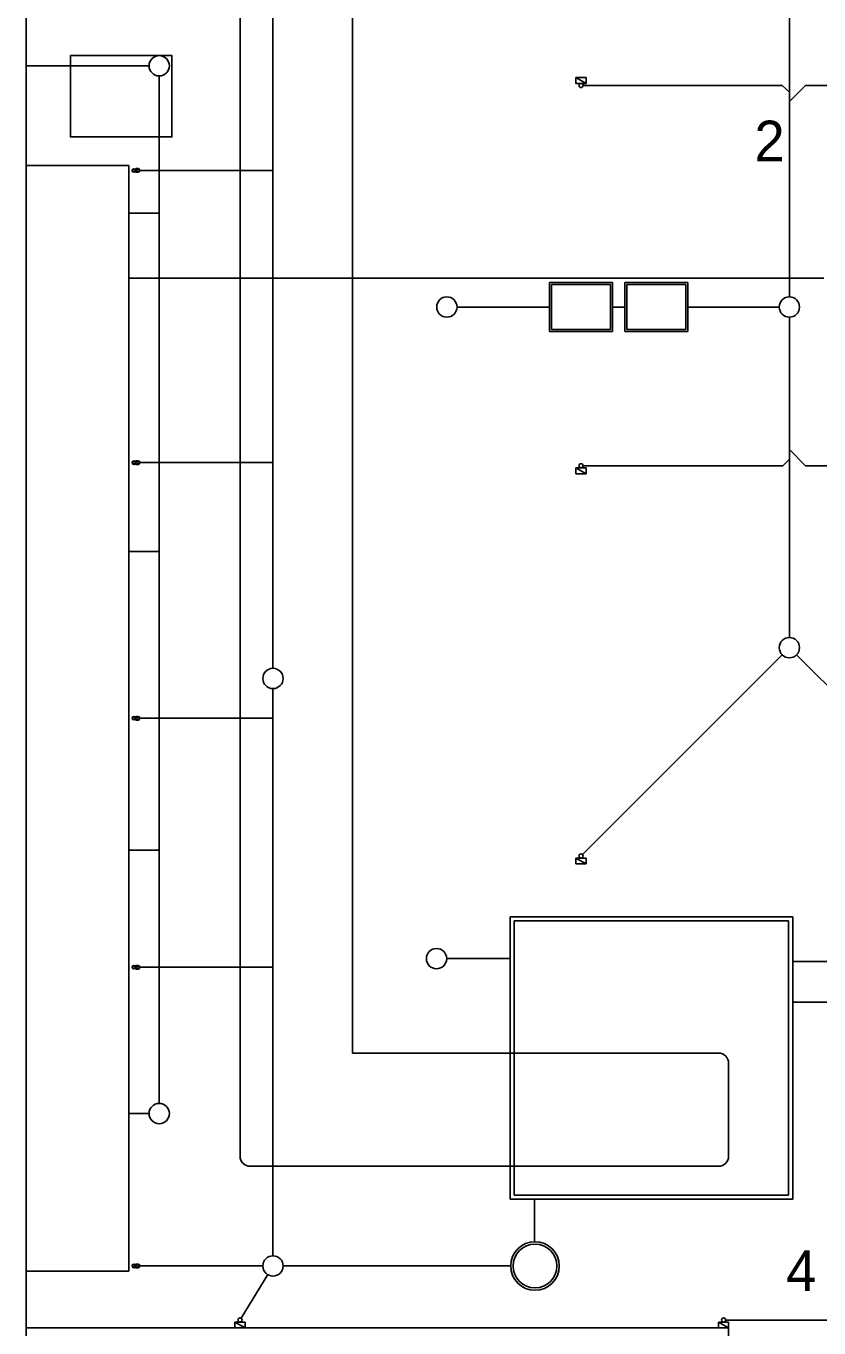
# Model space of a CAD drawing. Extents: x -263964 to -263544, y -1242317 to -1242020.
# Drawn here: x -263964.1 to -263925.1, y -1242255 to -1242190.9 of the extents above; entities that cross this region are included whole.
import ezdxf

# ---------------------------------------------------------------- set-up
doc = ezdxf.new("R2010")
doc.units = 0
for name, color, linetype in [('KFA_KOORDINACNA_SITUACIA_DSP_SEDA', 7, 'Continuous'), ('KFA_SO_50-2_POZIARNY_VODOVOD_BODY', 7, 'Continuous'), ('RAM_NA_TLAC_A3_1-100', 7, 'Continuous')]:
    doc.layers.add(name, color=color, linetype=linetype)

msp = doc.modelspace()

# ---------------------------------------------------------------- linework, layer by layer
at = {"layer": 'KFA_KOORDINACNA_SITUACIA_DSP_SEDA'}
for p, q in [((-263948.093, -1242087.901), (-263948.093, -1242241.458)), ((-263953.617, -1242244.458), (-263953.617, -1242093.307)), ((-263926.593, -1242155.252), (-263926.593, -1242204.252)), ((-263952, -1242222.527), (-263952, -1242182)), ((-263958.097, -1242192.883), (-263964.149, -1242192.883)), ((-263957.597, -1242243.932), (-263957.597, -1242193.383)), ((-263937.093, -1242193.752), (-263937.093, -1242193.462)), ((-263937.093, -1242193.462), (-263936.593, -1242193.462)), ((-263936.593, -1242193.752), (-263937.093, -1242193.462)), ((-263936.593, -1242193.752), (-263937.093, -1242193.462)), ((-263937.093, -1242193.462), (-263937.093, -1242193.752)), ((-263936.593, -1242193.752), (-263937.093, -1242193.752)), ((-263937.093, -1242193.752), (-263936.593, -1242193.752)), ((-263936.743, -1242193.852), (-263926.953, -1242193.852)), ((-263936.593, -1242193.462), (-263936.593, -1242193.752)), ((-263926.953, -1242193.852), (-263926.593, -1242194.178)), ((-263925.798, -1242193.852), (-263926.593, -1242194.648)), ((-263920.944, -1242193.852), (-263925.798, -1242193.852)), ((-263964.149, -1242197.782), (-263959.093, -1242197.782)), ((-263964.149, -1242197.782), (-263959.097, -1242197.782)), ((-263964.149, -1242252.182), (-263964.149, -1242197.782)), ((-263964.149, -1242197.782), (-263959.097, -1242197.782)), ((-263959.097, -1242197.782), (-263959.093, -1242252.182)), ((-263959.097, -1242197.782), (-263959.097, -1242252.182)), ((-263959.093, -1242197.782), (-263959.093, -1242252.182)), ((-263958.799, -1242197.962), (-263958.762, -1242197.962)), ((-263958.799, -1242198.102), (-263958.762, -1242198.102)), ((-263958.762, -1242197.962), (-263958.742, -1242197.942)), ((-263958.762, -1242198.102), (-263958.742, -1242198.122)), ((-263958.742, -1242197.942), (-263958.637, -1242197.942)), ((-263958.742, -1242198.122), (-263958.637, -1242198.122)), ((-263958.575, -1242198.032), (-263952, -1242198.032)), ((-263959.097, -1242200.132), (-263957.597, -1242200.132)), ((-263959.097, -1242203.332), (-263958.097, -1242203.332)), ((-263924.893, -1242203.332), (-263958.097, -1242203.332)), ((-263938.393, -1242203.552), (-263935.293, -1242203.552)), ((-263938.393, -1242205.952), (-263938.393, -1242203.552)), ((-263938.293, -1242205.852), (-263938.293, -1242203.652)), ((-263938.293, -1242203.652), (-263935.393, -1242203.652)), ((-263935.393, -1242205.852), (-263935.393, -1242203.652)), ((-263935.293, -1242205.952), (-263935.293, -1242203.552)), ((-263934.693, -1242203.552), (-263931.593, -1242203.552)), ((-263934.693, -1242203.552), (-263934.693, -1242205.952)), ((-263934.593, -1242203.652), (-263934.593, -1242205.852)), ((-263934.593, -1242203.652), (-263931.693, -1242203.652)), ((-263931.693, -1242203.652), (-263931.693, -1242205.852)), ((-263931.593, -1242203.552), (-263931.593, -1242205.952)), ((-263938.393, -1242204.752), (-263942.945, -1242204.752)), ((-263934.693, -1242204.752), (-263935.293, -1242204.752)), ((-263927.093, -1242204.752), (-263931.593, -1242204.752)), ((-263926.593, -1242221.011), (-263926.593, -1242205.252)), ((-263935.293, -1242205.952), (-263938.393, -1242205.952)), ((-263935.393, -1242205.852), (-263938.293, -1242205.852)), ((-263931.593, -1242205.952), (-263934.693, -1242205.952)), ((-263931.693, -1242205.852), (-263934.593, -1242205.852)), ((-263925.798, -1242212.562), (-263926.593, -1242211.767)), ((-263958.799, -1242212.337), (-263958.762, -1242212.337)), ((-263958.762, -1242212.337), (-263958.742, -1242212.317)), ((-263958.742, -1242212.317), (-263958.637, -1242212.317)), ((-263958.575, -1242212.407), (-263952, -1242212.407)), ((-263926.919, -1242212.562), (-263926.593, -1242212.237)), ((-263958.799, -1242212.477), (-263958.762, -1242212.477)), ((-263958.762, -1242212.477), (-263958.742, -1242212.497)), ((-263958.742, -1242212.497), (-263958.637, -1242212.497)), ((-263937.093, -1242212.952), (-263937.093, -1242212.662)), ((-263937.093, -1242212.662), (-263936.593, -1242212.662)), ((-263936.593, -1242212.952), (-263937.093, -1242212.662)), ((-263936.593, -1242212.952), (-263937.093, -1242212.662)), ((-263937.093, -1242212.662), (-263937.093, -1242212.952)), ((-263936.593, -1242212.952), (-263937.093, -1242212.952)), ((-263937.093, -1242212.952), (-263936.593, -1242212.952)), ((-263936.743, -1242212.562), (-263926.919, -1242212.562)), ((-263936.593, -1242212.662), (-263936.593, -1242212.952)), ((-263916.443, -1242212.562), (-263925.798, -1242212.562)), ((-263959.097, -1242216.782), (-263957.597, -1242216.782)), ((-263936.772, -1242231.691), (-263926.947, -1242221.865)), ((-263916.414, -1242231.691), (-263926.24, -1242221.865)), ((-263952, -1242251.432), (-263952, -1242223.527)), ((-263958.799, -1242224.912), (-263958.762, -1242224.912)), ((-263958.799, -1242225.052), (-263958.762, -1242225.052)), ((-263958.762, -1242224.912), (-263958.742, -1242224.892)), ((-263958.762, -1242225.052), (-263958.742, -1242225.072)), ((-263958.742, -1242224.892), (-263958.637, -1242224.892)), ((-263958.742, -1242225.072), (-263958.637, -1242225.072)), ((-263958.575, -1242224.982), (-263952, -1242224.982)), ((-263959.097, -1242231.482), (-263957.597, -1242231.482)), ((-263937.093, -1242231.862), (-263936.593, -1242231.862)), ((-263937.093, -1242232.152), (-263937.093, -1242231.862)), ((-263937.093, -1242231.862), (-263936.593, -1242232.152)), ((-263937.093, -1242231.862), (-263936.593, -1242232.152)), ((-263936.593, -1242231.862), (-263937.093, -1242231.862)), ((-263936.593, -1242232.152), (-263937.093, -1242232.152)), ((-263936.593, -1242231.862), (-263936.593, -1242232.152)), ((-263936.593, -1242232.152), (-263936.593, -1242231.862)), ((-263926.43, -1242234.749), (-263940.33, -1242234.749)), ((-263940.33, -1242234.749), (-263940.33, -1242248.649)), ((-263926.43, -1242248.649), (-263926.43, -1242234.749)), ((-263926.63, -1242234.949), (-263940.13, -1242234.949)), ((-263940.13, -1242234.949), (-263940.13, -1242248.449)), ((-263926.63, -1242248.449), (-263926.63, -1242234.949)), ((-263958.799, -1242237.162), (-263958.762, -1242237.162)), ((-263958.799, -1242237.302), (-263958.762, -1242237.302)), ((-263958.762, -1242237.162), (-263958.742, -1242237.142)), ((-263958.762, -1242237.302), (-263958.742, -1242237.322)), ((-263958.742, -1242237.142), (-263958.637, -1242237.142)), ((-263958.742, -1242237.322), (-263958.637, -1242237.322)), ((-263958.575, -1242237.232), (-263952, -1242237.232)), ((-263940.33, -1242236.811), (-263943.454, -1242236.811)), ((-263919.13, -1242236.949), (-263926.43, -1242236.949)), ((-263907.219, -1242238.949), (-263926.43, -1242238.949)), ((-263930.081, -1242241.458), (-263948.093, -1242241.458)), ((-263929.582, -1242246.53), (-263929.581, -1242241.959)), ((-263959.097, -1242244.432), (-263958.097, -1242244.432)), ((-263953.617, -1242244.458), (-263953.619, -1242246.529)), ((-263953.119, -1242247.03), (-263930.082, -1242247.03)), ((-263940.33, -1242248.649), (-263926.43, -1242248.649)), ((-263940.13, -1242248.449), (-263926.63, -1242248.449)), ((-263939.13, -1242248.649), (-263939.13, -1242250.737)), ((-263958.799, -1242251.862), (-263958.762, -1242251.862)), ((-263958.799, -1242252.002), (-263958.762, -1242252.002)), ((-263958.762, -1242251.862), (-263958.742, -1242251.842)), ((-263958.762, -1242252.002), (-263958.742, -1242252.022)), ((-263958.742, -1242251.842), (-263958.637, -1242251.842)), ((-263958.742, -1242252.022), (-263958.637, -1242252.022)), ((-263958.575, -1242251.932), (-263952.5, -1242251.932)), ((-263940.302, -1242251.932), (-263951.5, -1242251.932)), ((-263959.093, -1242252.182), (-263964.149, -1242252.182)), ((-263959.093, -1242252.182), (-263964.149, -1242252.182)), ((-263959.097, -1242252.182), (-263964.149, -1242252.182)), ((-263953.57, -1242254.506), (-263952.26, -1242252.359)), ((-263953.87, -1242254.692), (-263953.37, -1242254.692)), ((-263953.87, -1242254.982), (-263953.87, -1242254.692)), ((-263953.87, -1242254.692), (-263953.37, -1242254.982)), ((-263953.87, -1242254.692), (-263953.37, -1242254.982)), ((-263953.37, -1242254.692), (-263953.87, -1242254.692)), ((-263953.37, -1242254.692), (-263953.37, -1242254.982)), ((-263953.37, -1242254.982), (-263953.37, -1242254.692)), ((-263930.08, -1242254.692), (-263929.58, -1242254.692)), ((-263930.08, -1242254.982), (-263930.08, -1242254.692)), ((-263930.08, -1242254.692), (-263929.58, -1242254.982)), ((-263930.08, -1242254.692), (-263929.58, -1242254.982)), ((-263929.58, -1242254.692), (-263930.08, -1242254.692)), ((-263929.73, -1242254.592), (-263920.595, -1242254.592)), ((-263929.58, -1242254.692), (-263929.58, -1242254.982)), ((-263929.58, -1242254.982), (-263929.58, -1242254.692)), ((-263953.37, -1242254.982), (-263953.87, -1242254.982)), ((-263929.58, -1242254.982), (-263930.08, -1242254.982))]:
    msp.add_line(p, q, dxfattribs=at)
msp.add_lwpolyline([(-263961.968, -1242192.382), (-263956.968, -1242192.382), (-263956.968, -1242196.382), (-263961.968, -1242196.382)], close=True, dxfattribs=at)
for points in [[(-263929.58, -1242254.982), (-263964.149, -1242254.982)], [(-263964.149, -1242263.982), (-263929.58, -1242263.982), (-263929.58, -1242254.982)]]:
    msp.add_lwpolyline(points, dxfattribs=at)
for centre, radius in [((-263957.597, -1242192.883), 0.5), ((-263936.843, -1242193.852), 0.1), ((-263958.847, -1242198.032), 0.085), ((-263958.847, -1242198.032), 0.0625), ((-263958.637, -1242198.032), 0.0625), ((-263943.445, -1242204.752), 0.5), ((-263926.593, -1242204.752), 0.5), ((-263958.847, -1242212.407), 0.085), ((-263958.847, -1242212.407), 0.0625), ((-263958.637, -1242212.407), 0.0625), ((-263936.843, -1242212.562), 0.1), ((-263926.593, -1242221.511), 0.5), ((-263952, -1242223.027), 0.5), ((-263958.847, -1242224.982), 0.085), ((-263958.847, -1242224.982), 0.0625), ((-263958.637, -1242224.982), 0.0625), ((-263936.843, -1242231.762), 0.1), ((-263943.954, -1242236.811), 0.5), ((-263958.847, -1242237.232), 0.085), ((-263958.847, -1242237.232), 0.0625), ((-263958.637, -1242237.232), 0.0625), ((-263957.597, -1242244.432), 0.5), ((-263939.107, -1242251.932), 1.195), ((-263939.107, -1242251.932), 1.075), ((-263952, -1242251.932), 0.5), ((-263958.847, -1242251.932), 0.085), ((-263958.847, -1242251.932), 0.0625), ((-263958.637, -1242251.932), 0.0625), ((-263953.62, -1242254.592), 0.1), ((-263929.83, -1242254.592), 0.1)]:
    msp.add_circle(centre, radius, dxfattribs=at)
for centre, radius, start, end in [((-263958.637, -1242198.032), 0.09, 270, 90), ((-263958.637, -1242212.407), 0.09, 270, 90), ((-263958.637, -1242224.982), 0.09, 270, 90), ((-263958.637, -1242237.232), 0.09, 270, 90), ((-263930.081, -1242241.958), 0.5, 359.97854, 89.99994), ((-263953.119, -1242246.53), 0.5, 179.95255, 270), ((-263930.082, -1242246.53), 0.5, 270, 359.97854), ((-263958.637, -1242251.932), 0.09, 270, 90)]:
    msp.add_arc(centre, radius, start, end, dxfattribs=at)
at = {"layer": 'RAM_NA_TLAC_A3_1-100'}
msp.add_lwpolyline([(-263964.149, -1242020.359), (-263544.149, -1242020.359), (-263544.149, -1242317.359), (-263964.149, -1242317.359)], close=True, dxfattribs=at)

# ---------------------------------------------------------------- texts
at = {"layer": 'KFA_SO_50-2_POZIARNY_VODOVOD_BODY'}
for s, p in [('2', (-263928.312, -1242197.583)), ('4', (-263926.753, -1242253.169))]:
    msp.add_text(s, height=2, dxfattribs=at).set_placement(p)

doc.saveas('drawing.dxf')
